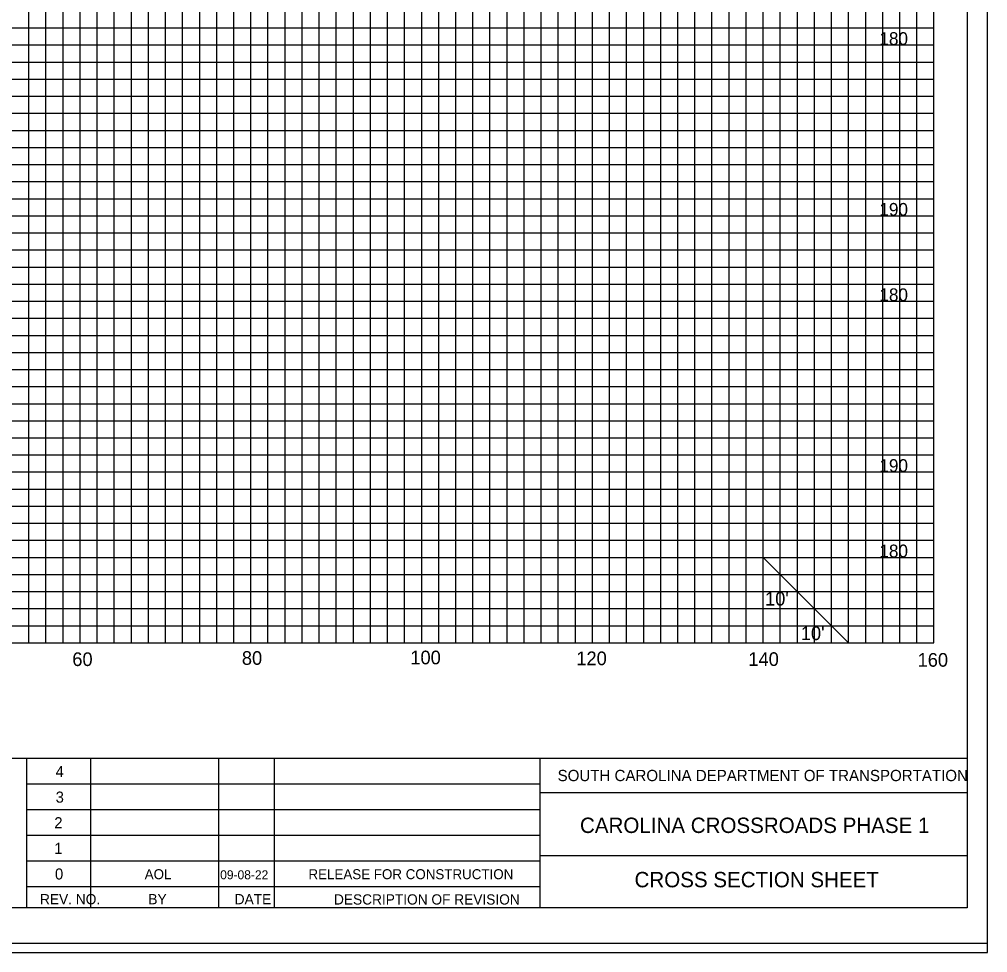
# Model space of a CAD drawing. Extents: x 967 to 1326, y 964 to 1184.
# Drawn here: x 1212.9 to 1326.3, y 963.7 to 1073 of the extents above; entities that cross this region are included whole.
import ezdxf

# ---------------------------------------------------------------- set-up
doc = ezdxf.new("R2010")
doc.units = 0
for name, color, linetype in [('Default', 7, 'Continuous'), ('RD_SHT_Bndy', 7, 'Continuous'), ('RD_SHT_IplotShp', 7, 'Continuous'), ('RD_SHT_Misc1', 7, 'Continuous'), ('RD_SHT_MjGrid', 7, 'Continuous'), ('RD_SHT_MnGrid', 7, 'Continuous'), ('RD_SHT_TX', 7, 'Continuous'), ('RD_Sketch1', 7, 'Continuous')]:
    doc.layers.add(name, color=color, linetype=linetype)

msp = doc.modelspace()

# ---------------------------------------------------------------- linework, layer by layer
at = {"layer": 'RD_SHT_Bndy'}
for p, q in [((1323.89, 1178.46), (1323.89, 968.98)), ((996.11, 986.49), (1323.89, 986.49)), ((1213.76, 968.94), (1213.76, 986.49)), ((1221.26, 968.95), (1221.26, 986.48)), ((1236.26, 968.95), (1236.26, 986.48)), ((1242.76, 968.95), (1242.76, 986.48)), ((1273.88, 968.98), (1273.88, 986.49)), ((1213.76, 983.48), (1273.88, 983.48)), ((1323.93, 982.43), (1273.88, 982.43)), ((1213.76, 980.48), (1273.88, 980.48)), ((1213.76, 977.48), (1273.88, 977.48)), ((1213.76, 974.48), (1273.88, 974.48)), ((1323.89, 975.04), (1273.88, 975.04)), ((1213.76, 971.48), (1273.88, 971.48)), ((1323.89, 968.98), (996.11, 968.98))]:
    msp.add_line(p, q, dxfattribs=at)
at = {"layer": 'RD_SHT_IplotShp'}
for points in [[(967.41, 963.72), (1326.28, 963.72), (1326.28, 1183.72), (967.41, 1183.72)], [(988.52, 964.84), (1326.28, 964.84), (1326.28, 1182.6), (988.52, 1182.6)]]:
    msp.add_lwpolyline(points, close=True, dxfattribs=at)
at = {"layer": 'RD_SHT_MjGrid'}
for p, q in [((1220, 1000), (1220, 1170)), ((1230, 1000), (1230, 1170)), ((1240, 1000), (1240, 1170)), ((1250, 1000), (1250, 1170)), ((1260, 1000), (1260, 1170)), ((1270, 1000), (1270, 1170)), ((1280, 1000), (1280, 1170)), ((1290, 1000), (1290, 1170)), ((1300, 1000), (1300, 1170)), ((1310, 1000), (1310, 1170)), ((1320, 1000), (1320, 1170)), ((1000, 1070), (1320, 1070)), ((1000, 1060), (1320, 1060)), ((1000, 1050), (1320, 1050)), ((1000, 1040), (1320, 1040)), ((1000, 1030), (1320, 1030)), ((1000, 1020), (1320, 1020)), ((1000, 1010), (1320, 1010)), ((1000, 1000), (1320, 1000))]:
    msp.add_line(p, q, dxfattribs=at)
at = {"layer": 'RD_SHT_MnGrid'}
for p, q in [((1214, 1000), (1214, 1170)), ((1216, 1000), (1216, 1170)), ((1218, 1000), (1218, 1170)), ((1222, 1000), (1222, 1170)), ((1224, 1000), (1224, 1170)), ((1226, 1000), (1226, 1170)), ((1228, 1000), (1228, 1170)), ((1232, 1000), (1232, 1170)), ((1234, 1000), (1234, 1170)), ((1236, 1000), (1236, 1170)), ((1238, 1000), (1238, 1170)), ((1242, 1000), (1242, 1170)), ((1244, 1000), (1244, 1170)), ((1246, 1000), (1246, 1170)), ((1248, 1000), (1248, 1170)), ((1252, 1000), (1252, 1170)), ((1254, 1000), (1254, 1170)), ((1256, 1000), (1256, 1170)), ((1258, 1000), (1258, 1170)), ((1262, 1000), (1262, 1170)), ((1264, 1000), (1264, 1170)), ((1266, 1000), (1266, 1170)), ((1268, 1000), (1268, 1170)), ((1272, 1000), (1272, 1170)), ((1274, 1000), (1274, 1170)), ((1276, 1000), (1276, 1170)), ((1278, 1000), (1278, 1170)), ((1282, 1000), (1282, 1170)), ((1284, 1000), (1284, 1170)), ((1286, 1000), (1286, 1170)), ((1288, 1000), (1288, 1170)), ((1292, 1000), (1292, 1170)), ((1294, 1000), (1294, 1170)), ((1296, 1000), (1296, 1170)), ((1298, 1000), (1298, 1170)), ((1302, 1000), (1302, 1170)), ((1304, 1000), (1304, 1170)), ((1306, 1000), (1306, 1170)), ((1308, 1000), (1308, 1170)), ((1312, 1000), (1312, 1170)), ((1314, 1000), (1314, 1170)), ((1316, 1000), (1316, 1170)), ((1318, 1000), (1318, 1170)), ((1000, 1072), (1320, 1072)), ((1000, 1068), (1320, 1068)), ((1000, 1066), (1320, 1066)), ((1000, 1064), (1320, 1064)), ((1000, 1062), (1320, 1062)), ((1000, 1058), (1320, 1058)), ((1000, 1056), (1320, 1056)), ((1000, 1054), (1320, 1054)), ((1000, 1052), (1320, 1052)), ((1000, 1048), (1320, 1048)), ((1000, 1046), (1320, 1046)), ((1000, 1044), (1320, 1044)), ((1000, 1042), (1320, 1042)), ((1000, 1038), (1320, 1038)), ((1000, 1036), (1320, 1036)), ((1000, 1034), (1320, 1034)), ((1000, 1032), (1320, 1032)), ((1000, 1028), (1320, 1028)), ((1000, 1026), (1320, 1026)), ((1000, 1024), (1320, 1024)), ((1000, 1022), (1320, 1022)), ((1000, 1018), (1320, 1018)), ((1000, 1016), (1320, 1016)), ((1000, 1014), (1320, 1014)), ((1000, 1012), (1320, 1012)), ((1000, 1008), (1320, 1008)), ((1000, 1006), (1320, 1006)), ((1000, 1004), (1320, 1004)), ((1000, 1002), (1320, 1002))]:
    msp.add_line(p, q, dxfattribs=at)
at = {"layer": 'RD_SHT_TX'}
msp.add_line((1300, 1010), (1310, 1000), dxfattribs=at)
at = {"layer": 'RD_Sketch1'}
msp.add_lwpolyline([(967.41, 963.72), (1326.28, 963.72), (1326.28, 1183.72), (967.41, 1183.72)], close=True, dxfattribs=at)

# ---------------------------------------------------------------- texts
at = {"layer": 'Default'}
for s, p in [('180', (1313.61, 1070)), ('190', (1313.61, 1050)), ('180', (1313.61, 1040)), ('190', (1313.61, 1020)), ('180', (1313.61, 1010))]:
    msp.add_text(s, height=1.5, dxfattribs=at).set_placement(p)
at = {"layer": 'RD_SHT_Misc1'}
for s, height, p in [('AOL', 1.17, (1227.56, 972.32)), ('09-08-22', 1.053, (1236.4, 972.31)), ('RELEASE FOR CONSTRUCTION', 1.17, (1246.74, 972.32))]:
    msp.add_text(s, height=height, dxfattribs=at).set_placement(p)
at = {"layer": 'RD_SHT_TX'}
for s, height, p in [("10'", 1.6, (1300.21, 1004.36)), ("10'", 1.6, (1304.4, 1000.32)), ('100', 1.6, (1258.67, 997.48)), ('60', 1.6, (1219.08, 997.28)), ('80', 1.6, (1238.94, 997.42)), ('120', 1.6, (1278.11, 997.38)), ('140', 1.6, (1298.26, 997.29)), ('160', 1.6, (1318.08, 997.2)), ('4', 1.3, (1217.13, 984.28)), ('SOUTH CAROLINA DEPARTMENT OF TRANSPORTATION', 1.32, (1275.92, 983.8)), ('3', 1.3, (1217.13, 981.28)), ('2', 1.3, (1216.97, 978.28)), ('1', 1.3, (1216.97, 975.28)), ('0', 1.3, (1217.05, 972.28)), ('REV. NO.', 1.2, (1215.3, 969.38)), ('BY', 1.2, (1227.99, 969.38)), ('DATE', 1.2, (1238.1, 969.38)), ('DESCRIPTION OF REVISION', 1.2, (1249.73, 969.35))]:
    msp.add_text(s, height=height, dxfattribs=at).set_placement(p)
for s, p in [('CAROLINA CROSSROADS PHASE 1', (1278.54, 977.73)), ('CROSS SECTION SHEET', (1284.93, 971.37))]:
    msp.add_text(s, height=1.8, rotation=0, dxfattribs=at).set_placement(p)

doc.saveas('drawing.dxf')
